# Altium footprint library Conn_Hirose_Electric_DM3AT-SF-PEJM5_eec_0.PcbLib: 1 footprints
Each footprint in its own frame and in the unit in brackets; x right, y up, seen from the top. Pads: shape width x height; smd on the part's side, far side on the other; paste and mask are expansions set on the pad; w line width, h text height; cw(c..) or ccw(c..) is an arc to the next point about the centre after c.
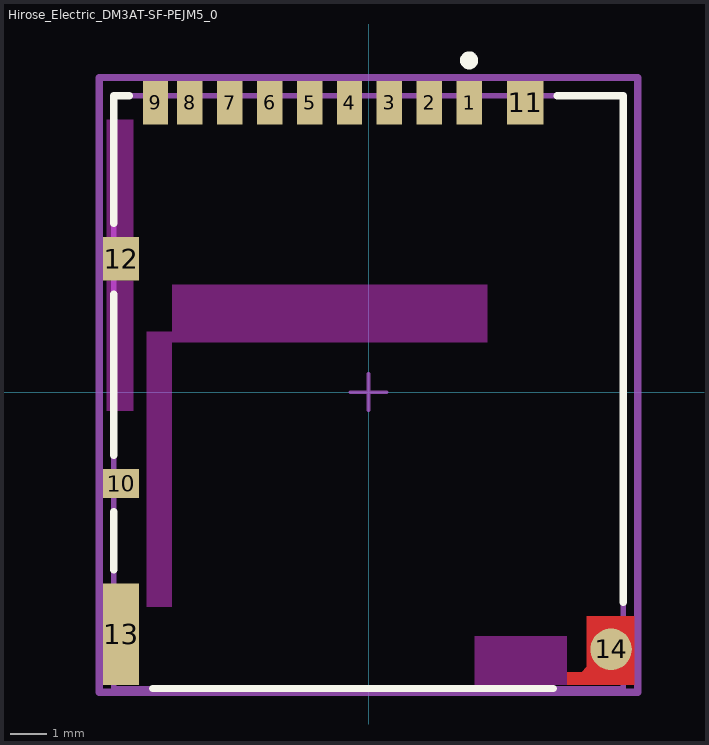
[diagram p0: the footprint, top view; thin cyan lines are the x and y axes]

## Hirose_Electric_DM3AT-SF-PEJM5_0 [mm]
pads (14):
  rect 0.7x1.2 smd paste+0 mask+0: 1(2.775,7.975) 2(1.675,7.975) 3(0.575,7.975) 4(-0.525,7.975) 5(-1.625,7.975) 6(-2.725,7.975) 7(-3.825,7.975) 8(-4.925,7.975) 9(-5.875,7.975)
  rect 1x0.8 smd paste+0 mask+0: 10(-6.825,-2.525)
  rect 1x1.2 smd paste+0 mask+0: 11(4.325,7.975) 12(-6.825,3.675)
  rect 1x2.8 smd paste+0 mask+0: 13(-6.825,-6.675)
  round 1.145 smd paste+0 mask+0: 14(6.689,-7.092)
Top Layer:
  region: 6.025,-6.175 7.325,-6.175 7.325,-8.075 5.475,-8.075 5.475,-7.725 5.875,-7.725 6.025,-7.575
Top Overlay:
  circle w0.25: c2.775,9.15 r0.125
  lines w0.2: -7.025,-4.9 -7.025,-3.3 ; -7.025,-1.75 -7.025,2.7 ; -7.025,4.65 -7.025,8.175 -6.6,8.175 ; -5.95,-8.175 5.1,-8.175 ; 5.2,8.175 7.025,8.175 7.025,-5.8
Keep-Out Layer:
  rectangle: -7.225,4.275 -6.475,7.525
  rectangle: -7.225,-0.525 -6.475,3.075
  rectangle: -6.125,-5.925 -5.425,1.675
  rectangle: -5.425,1.375 3.275,2.975
  rectangle: 2.925,-8.075 5.475,-6.725
Mechanical 10:
  lines w0.2: -7.425,-8.275 7.425,-8.275 7.425,8.675 -7.425,8.675 -7.425,-8.275
  text ".Designator" at 0,0.2 h1
Mechanical 12:
  lines w0.15: -7.025,-8.175 7.025,-8.175 7.025,8.175 -7.025,8.175 -7.025,-8.175
Mechanical 15:
  lines w0.1: -0.5,0 0.5,0 ; 0,-0.5 0,0.5
  lines w0.2: -7.425,-8.275 7.425,-8.275 7.425,8.675 -7.425,8.675 -7.425,-8.275
3D body "Conn_Hirose_Electric_DM3AT-SF-PEJM5_eec.STEP": height 0.25, standoff 0, extent -7.425,-8.275 7.425,8.675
